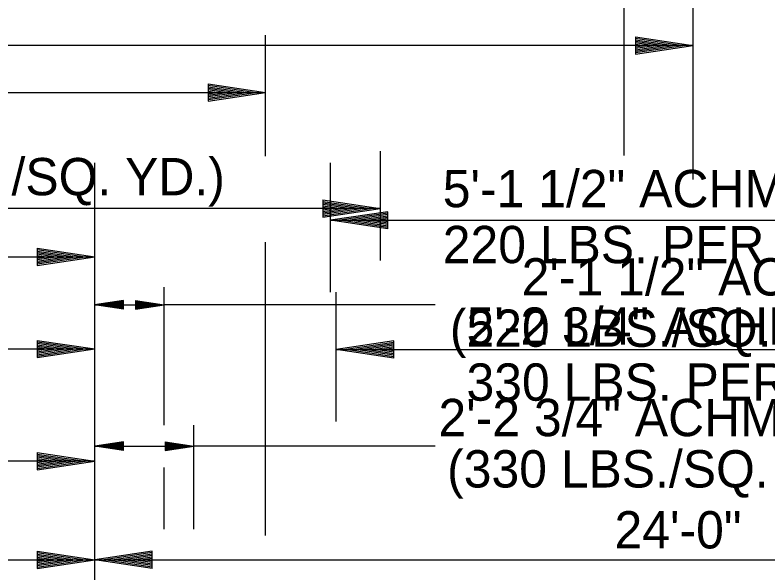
# Model space of a CAD drawing. Extents: x 1373719 to 1374161, y 379835 to 380167.
# Drawn here: x 1373973.66 to 1373986.78, y 380119.77 to 380129.49 of the extents above; entities that cross this region are included whole.
import ezdxf

# ---------------------------------------------------------------- set-up
doc = ezdxf.new("R2010")
doc.units = 0
doc.layers.add('GREEN_TXT', color=7, linetype='Continuous')
doc.layers.add('Text 1', color=7, linetype='Continuous')

msp = doc.modelspace()

# ---------------------------------------------------------------- linework, layer by layer
at = {"layer": 'GREEN_TXT'}
for p, q in [((1373985.467, 380130.103), (1373985.467, 380126.626)), ((1373984.467, 380129.112), (1373985.467, 380128.962)), ((1373984.467, 380129.112), (1373984.467, 380128.812)), ((1373984.467, 380129.087), (1373985.3, 380128.962)), ((1373984.467, 380129.062), (1373985.128, 380128.962)), ((1373984.467, 380129.037), (1373984.962, 380128.962)), ((1373984.467, 380129.011), (1373984.792, 380128.962)), ((1373985.467, 380128.962), (1373944.572, 380128.962)), ((1373984.467, 380128.986), (1373984.625, 380128.962)), ((1373984.467, 380128.812), (1373985.467, 380128.962)), ((1373984.467, 380128.913), (1373984.792, 380128.962)), ((1373984.467, 380128.863), (1373985.128, 380128.962)), ((1373984.467, 380128.837), (1373985.3, 380128.962)), ((1373984.467, 380128.888), (1373984.962, 380128.962)), ((1373984.467, 380128.939), (1373984.625, 380128.962)), ((1373980.02, 380127.121), (1373980.02, 380125.214)), ((1373979.02, 380126.271), (1373980.02, 380126.121)), ((1373979.02, 380126.271), (1373979.02, 380125.971)), ((1373979.02, 380126.246), (1373979.853, 380126.121)), ((1373980.02, 380126.121), (1373950.02, 380126.121)), ((1373979.02, 380126.22), (1373979.681, 380126.121)), ((1373979.02, 380126.195), (1373979.515, 380126.121)), ((1373979.02, 380126.169), (1373979.345, 380126.121)), ((1373979.02, 380126.144), (1373979.178, 380126.121)), ((1373979.02, 380125.971), (1373980.02, 380126.121)), ((1373979.02, 380126.072), (1373979.345, 380126.121)), ((1373979.02, 380126.021), (1373979.681, 380126.121)), ((1373979.02, 380125.996), (1373979.853, 380126.121)), ((1373979.02, 380126.046), (1373979.515, 380126.121)), ((1373979.02, 380126.097), (1373979.178, 380126.121)), ((1373975.044, 380122.166), (1373975.044, 380124.701)), ((1373976.254, 380122.346), (1373976.254, 380124.751)), ((1373975.543, 380124.517), (1373975.043, 380124.442)), ((1373975.043, 380124.442), (1373976.254, 380124.442)), ((1373975.543, 380124.367), (1373975.043, 380124.442)), ((1373975.543, 380124.504), (1373975.127, 380124.442)), ((1373975.543, 380124.379), (1373975.127, 380124.442)), ((1373975.543, 380124.491), (1373975.213, 380124.442)), ((1373975.543, 380124.392), (1373975.213, 380124.442)), ((1373975.543, 380124.479), (1373975.296, 380124.442)), ((1373975.543, 380124.404), (1373975.296, 380124.442)), ((1373975.543, 380124.466), (1373975.381, 380124.442)), ((1373975.543, 380124.417), (1373975.381, 380124.442)), ((1373975.543, 380124.453), (1373975.464, 380124.442)), ((1373975.543, 380124.43), (1373975.464, 380124.442)), ((1373975.543, 380124.367), (1373975.543, 380124.517)), ((1373975.754, 380124.517), (1373976.254, 380124.442)), ((1373975.754, 380124.517), (1373975.754, 380124.367)), ((1373975.754, 380124.504), (1373976.171, 380124.442)), ((1373975.754, 380124.491), (1373976.085, 380124.442)), ((1373975.754, 380124.479), (1373976.002, 380124.442)), ((1373975.754, 380124.466), (1373975.917, 380124.442)), ((1373975.754, 380124.453), (1373975.833, 380124.442)), ((1373975.754, 380124.367), (1373976.254, 380124.442)), ((1373975.754, 380124.417), (1373975.917, 380124.442)), ((1373975.754, 380124.392), (1373976.085, 380124.442)), ((1373975.754, 380124.379), (1373976.171, 380124.442)), ((1373975.754, 380124.404), (1373976.002, 380124.442)), ((1373975.754, 380124.43), (1373975.833, 380124.442)), ((1373974.044, 380123.824), (1373975.044, 380123.674)), ((1373974.044, 380123.824), (1373974.044, 380123.524)), ((1373974.044, 380123.799), (1373974.877, 380123.674)), ((1373974.044, 380123.774), (1373974.705, 380123.674)), ((1373974.044, 380123.749), (1373974.539, 380123.674)), ((1373955.05, 380123.674), (1373975.044, 380123.674)), ((1373974.044, 380123.723), (1373974.369, 380123.674)), ((1373974.044, 380123.698), (1373974.202, 380123.674)), ((1373974.044, 380123.524), (1373975.044, 380123.674)), ((1373974.044, 380123.625), (1373974.369, 380123.674)), ((1373974.044, 380123.575), (1373974.705, 380123.674)), ((1373974.044, 380123.549), (1373974.877, 380123.674)), ((1373974.044, 380123.6), (1373974.539, 380123.674)), ((1373974.044, 380123.651), (1373974.202, 380123.674)), ((1373976.77, 380120.537), (1373976.77, 380122.346)), ((1373975.044, 380118.359), (1373975.044, 380122.166)), ((1373975.544, 380122.055), (1373975.044, 380121.98)), ((1373975.544, 380122.042), (1373975.128, 380121.98)), ((1373975.544, 380121.905), (1373975.544, 380122.055)), ((1373976.27, 380122.055), (1373976.77, 380121.98)), ((1373976.27, 380122.055), (1373976.27, 380121.905)), ((1373976.27, 380122.042), (1373976.687, 380121.98)), ((1373975.044, 380121.98), (1373976.77, 380121.98)), ((1373975.544, 380121.905), (1373975.044, 380121.98)), ((1373975.544, 380121.917), (1373975.128, 380121.98)), ((1373975.544, 380122.029), (1373975.214, 380121.98)), ((1373975.544, 380121.93), (1373975.214, 380121.98)), ((1373975.544, 380122.017), (1373975.297, 380121.98)), ((1373975.544, 380121.942), (1373975.297, 380121.98)), ((1373975.544, 380122.004), (1373975.382, 380121.98)), ((1373975.544, 380121.955), (1373975.382, 380121.98)), ((1373975.544, 380121.991), (1373975.465, 380121.98)), ((1373975.544, 380121.968), (1373975.465, 380121.98)), ((1373976.27, 380122.029), (1373976.601, 380121.98)), ((1373976.27, 380122.017), (1373976.517, 380121.98)), ((1373976.27, 380122.004), (1373976.433, 380121.98)), ((1373976.27, 380121.991), (1373976.349, 380121.98)), ((1373976.27, 380121.905), (1373976.77, 380121.98)), ((1373976.27, 380121.955), (1373976.433, 380121.98)), ((1373976.27, 380121.93), (1373976.601, 380121.98)), ((1373976.27, 380121.917), (1373976.687, 380121.98)), ((1373976.27, 380121.942), (1373976.517, 380121.98)), ((1373976.27, 380121.968), (1373976.349, 380121.98)), ((1373976.254, 380120.537), (1373976.254, 380121.61)), ((1373974.044, 380120.151), (1373975.044, 380120.001)), ((1373974.044, 380120.151), (1373974.044, 380119.851)), ((1373974.044, 380120.126), (1373974.877, 380120.001)), ((1373974.044, 380120.101), (1373974.705, 380120.001)), ((1373974.044, 380120.076), (1373974.539, 380120.001)), ((1373976.044, 380120.151), (1373975.044, 380120.001)), ((1373976.044, 380120.126), (1373975.211, 380120.001)), ((1373976.044, 380120.101), (1373975.383, 380120.001)), ((1373976.044, 380120.076), (1373975.55, 380120.001)), ((1373976.044, 380119.851), (1373976.044, 380120.151)), ((1373955.05, 380120.001), (1373975.044, 380120.001)), ((1373974.044, 380120.05), (1373974.369, 380120.001)), ((1373974.044, 380120.025), (1373974.202, 380120.001)), ((1373974.044, 380119.851), (1373975.044, 380120.001)), ((1373974.044, 380119.952), (1373974.369, 380120.001)), ((1373974.044, 380119.902), (1373974.705, 380120.001)), ((1373974.044, 380119.876), (1373974.877, 380120.001)), ((1373974.044, 380119.927), (1373974.539, 380120.001)), ((1373974.044, 380119.978), (1373974.202, 380120.001)), ((1373975.044, 380120.001), (1373996.075, 380120.001)), ((1373976.044, 380119.851), (1373975.044, 380120.001)), ((1373976.044, 380119.876), (1373975.211, 380120.001)), ((1373976.044, 380119.902), (1373975.383, 380120.001)), ((1373976.044, 380119.927), (1373975.55, 380120.001)), ((1373976.044, 380120.05), (1373975.719, 380120.001)), ((1373976.044, 380119.953), (1373975.719, 380120.001)), ((1373976.044, 380120.025), (1373975.886, 380120.001)), ((1373976.044, 380119.978), (1373975.886, 380120.001))]:
    msp.add_line(p, q, dxfattribs=at)
for points in [[(1373980.977, 380124.442), (1373976.254, 380124.442)], [(1373980.977, 380121.98), (1373976.77, 380121.98)]]:
    msp.add_lwpolyline(points, dxfattribs=at)
at = {"layer": 'Text 1'}
for p, q in [((1373984.268, 380127.044), (1373984.268, 380132.176)), ((1373978.016, 380129.144), (1373978.016, 380127.032)), ((1373977.02, 380128.294), (1373978.02, 380128.144)), ((1373977.02, 380128.294), (1373977.02, 380127.994)), ((1373977.02, 380128.269), (1373977.853, 380128.144)), ((1373977.02, 380128.244), (1373977.681, 380128.144)), ((1373977.02, 380128.219), (1373977.514, 380128.144)), ((1373952.02, 380128.144), (1373978.02, 380128.144)), ((1373977.02, 380128.193), (1373977.345, 380128.144)), ((1373977.02, 380128.168), (1373977.178, 380128.144)), ((1373977.02, 380127.994), (1373978.02, 380128.144)), ((1373977.02, 380128.095), (1373977.345, 380128.144)), ((1373977.02, 380128.045), (1373977.681, 380128.144)), ((1373977.02, 380128.019), (1373977.853, 380128.144)), ((1373977.02, 380128.07), (1373977.514, 380128.144)), ((1373977.02, 380128.121), (1373977.178, 380128.144)), ((1373975.044, 380118.358), (1373975.044, 380126.916)), ((1373979.15, 380124.662), (1373979.15, 380126.916)), ((1373980.15, 380126.066), (1373979.15, 380125.916)), ((1373980.15, 380126.041), (1373979.317, 380125.916)), ((1373980.15, 380126.015), (1373979.489, 380125.916)), ((1373980.15, 380125.99), (1373979.655, 380125.916)), ((1373980.15, 380125.766), (1373980.15, 380126.066)), ((1373980.15, 380125.766), (1373979.15, 380125.916)), ((1373979.15, 380125.916), (1373999.687, 380125.916)), ((1373980.15, 380125.791), (1373979.317, 380125.916)), ((1373980.15, 380125.816), (1373979.489, 380125.916)), ((1373980.15, 380125.841), (1373979.655, 380125.916)), ((1373980.15, 380125.965), (1373979.825, 380125.916)), ((1373980.15, 380125.867), (1373979.825, 380125.916)), ((1373980.15, 380125.939), (1373979.992, 380125.916)), ((1373980.15, 380125.892), (1373979.992, 380125.916)), ((1373978.016, 380125.538), (1373978.016, 380120.424)), ((1373974.044, 380125.43), (1373975.044, 380125.28)), ((1373974.044, 380125.43), (1373974.044, 380125.13)), ((1373974.044, 380125.405), (1373974.877, 380125.28)), ((1373974.044, 380125.38), (1373974.705, 380125.28)), ((1373974.044, 380125.355), (1373974.539, 380125.28)), ((1373974.044, 380125.329), (1373974.369, 380125.28)), ((1373955.046, 380125.279), (1373975.044, 380125.279)), ((1373974.044, 380125.304), (1373974.202, 380125.28)), ((1373974.044, 380125.13), (1373975.044, 380125.28)), ((1373974.044, 380125.231), (1373974.369, 380125.28)), ((1373974.044, 380125.181), (1373974.705, 380125.28)), ((1373974.044, 380125.155), (1373974.877, 380125.28)), ((1373974.044, 380125.206), (1373974.539, 380125.28)), ((1373974.044, 380125.257), (1373974.202, 380125.28)), ((1373979.254, 380122.412), (1373979.254, 380124.665)), ((1373980.254, 380123.815), (1373979.254, 380123.665)), ((1373980.254, 380123.79), (1373979.421, 380123.665)), ((1373980.254, 380123.765), (1373979.593, 380123.665)), ((1373980.254, 380123.74), (1373979.759, 380123.665)), ((1373980.254, 380123.515), (1373980.254, 380123.815)), ((1373980.254, 380123.515), (1373979.254, 380123.665)), ((1373979.254, 380123.665), (1373999.687, 380123.665)), ((1373980.254, 380123.54), (1373979.421, 380123.665)), ((1373980.254, 380123.566), (1373979.593, 380123.665)), ((1373980.254, 380123.591), (1373979.759, 380123.665)), ((1373980.254, 380123.714), (1373979.929, 380123.665)), ((1373980.254, 380123.617), (1373979.929, 380123.665)), ((1373980.254, 380123.689), (1373980.096, 380123.665)), ((1373980.254, 380123.642), (1373980.096, 380123.665)), ((1373974.044, 380121.868), (1373975.044, 380121.718)), ((1373974.044, 380121.868), (1373974.044, 380121.568)), ((1373974.044, 380121.843), (1373974.877, 380121.718)), ((1373974.044, 380121.818), (1373974.705, 380121.718)), ((1373974.044, 380121.793), (1373974.539, 380121.718)), ((1373975.044, 380121.718), (1373955.044, 380121.718)), ((1373974.044, 380121.767), (1373974.369, 380121.718)), ((1373974.044, 380121.742), (1373974.202, 380121.718)), ((1373974.044, 380121.568), (1373975.044, 380121.718)), ((1373974.044, 380121.669), (1373974.369, 380121.718)), ((1373974.044, 380121.619), (1373974.705, 380121.718)), ((1373974.044, 380121.593), (1373974.877, 380121.718)), ((1373974.044, 380121.644), (1373974.539, 380121.718)), ((1373974.044, 380121.695), (1373974.202, 380121.718))]:
    msp.add_line(p, q, dxfattribs=at)

# ---------------------------------------------------------------- texts
at = {"layer": 'GREEN_TXT'}
for s, p in [('(220 LBS./SQ. YD.)', (1373969.728, 380126.352)), ('2\'-1 1/2" ACHM SURFACE (1/2")', (1373982.484, 380124.606)), ('(220 LBS./SQ. YD.) & TACK COAT', (1373981.233, 380123.712)), ('2\'-2 3/4" ACHM BINDER COURSE (1")', (1373981.034, 380122.155)), ('(330 LBS./SQ. YD.) & TACK COAT', (1373981.185, 380121.261)), ('24\'-0"', (1373984.102, 380120.199))]:
    msp.add_text(s, height=0.65, dxfattribs=at).set_placement(p)
at = {"layer": 'Text 1'}
for s, p in [('5\'-1 1/2" ACHM SURFACE COURSE (1/2")', (1373981.109, 380126.144)), ('220 LBS. PER SQ. YD. & TACK COAT', (1373981.109, 380125.169)), ('5\'-2 3/4" ACHM BINDER COURSE (1")', (1373981.523, 380123.748)), ('330 LBS. PER SQ. YD. & TACK COAT', (1373981.523, 380122.773))]:
    msp.add_text(s, height=0.65, dxfattribs=at).set_placement(p)

doc.saveas('drawing.dxf')
